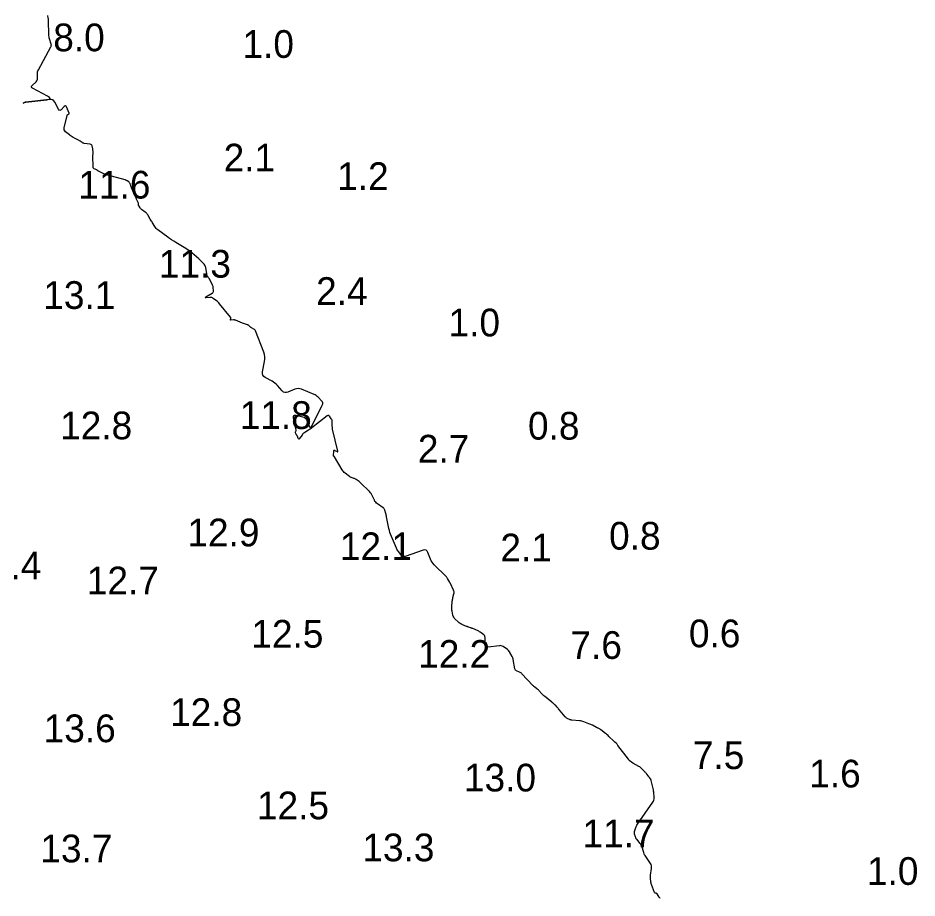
# Model space of a CAD drawing. Extents: x 815352 to 820877, y 582403 to 597439.
# Drawn here: x 817522 to 817684.3, y 596217.5 to 596376.3 of the extents above; entities that cross this region are included whole.
import ezdxf

# ---------------------------------------------------------------- set-up
doc = ezdxf.new("R2010")
doc.units = 0
doc.layers.add('V-CONT-EL12', color=7, linetype='Continuous')
doc.layers.add('V-TOPO-SOUN', color=7, linetype='Continuous')

msp = doc.modelspace()

# ---------------------------------------------------------------- linework, layer by layer
at = {"layer": 'V-CONT-EL12'}
msp.add_lwpolyline([(817637.89, 596217.43), (817637.81, 596217.54), (817637.73, 596217.65), (817637.33, 596218.27), (817637.3, 596218.31), (817637.27, 596218.34), (817637.23, 596218.36), (817637.19, 596218.37), (817637.01, 596218.41), (817636.97, 596218.42), (817636.94, 596218.44), (817636.91, 596218.47), (817636.89, 596218.51), (817636.33, 596219.95), (817636.29, 596220.09), (817636.25, 596220.22), (817636.22, 596220.36), (817636.21, 596220.5), (817636.17, 596221.07), (817636.16, 596221.22), (817636.16, 596221.36), (817636.17, 596221.5), (817636.18, 596221.64), (817636.34, 596222.85), (817636.36, 596223.09), (817636.32, 596223.32), (817636.25, 596223.55), (817636.14, 596223.76), (817635.21, 596225.17), (817635.1, 596225.34), (817635.01, 596225.52), (817634.93, 596225.71), (817634.87, 596225.9), (817634.63, 596226.69), (817634.56, 596226.87), (817634.48, 596227.05), (817634.38, 596227.22), (817634.26, 596227.38), (817633.66, 596228.13), (817633.59, 596228.23), (817633.53, 596228.33), (817633.48, 596228.44), (817633.43, 596228.56), (817633.28, 596229.03), (817633.25, 596229.15), (817633.24, 596229.26), (817633.25, 596229.38), (817633.28, 596229.5), (817633.49, 596230.23), (817633.55, 596230.39), (817633.61, 596230.54), (817633.69, 596230.68), (817633.78, 596230.82), (817636.56, 596234.79), (817636.67, 596234.99), (817636.75, 596235.2), (817636.79, 596235.42), (817636.8, 596235.65), (817636.74, 596236.6), (817636.72, 596236.83), (817636.69, 596237.06), (817636.65, 596237.29), (817636.59, 596237.52), (817636.28, 596238.72), (817636.26, 596238.8), (817636.23, 596238.87), (817636.19, 596238.94), (817636.15, 596239.01), (817635.96, 596239.26), (817635.92, 596239.33), (817635.87, 596239.39), (817635.82, 596239.45), (817635.77, 596239.52), (817635.48, 596239.9), (817635.42, 596239.98), (817635.35, 596240.06), (817635.28, 596240.14), (817635.21, 596240.22), (817634.62, 596240.84), (817634.49, 596240.96), (817634.35, 596241.07), (817634.21, 596241.17), (817634.06, 596241.26), (817632.95, 596241.87), (817632.73, 596242.01), (817632.52, 596242.17), (817632.33, 596242.36), (817632.16, 596242.56), (817630.28, 596245.04), (817630.11, 596245.26), (817629.93, 596245.46), (817629.74, 596245.66), (817629.55, 596245.85), (817628.65, 596246.68), (817628.49, 596246.82), (817628.34, 596246.96), (817628.19, 596247.09), (817628.03, 596247.22), (817627.18, 596247.9), (817627.13, 596247.95), (817627.07, 596247.98), (817627.01, 596248.02), (817626.95, 596248.05), (817626.69, 596248.17), (817626.62, 596248.19), (817626.56, 596248.23), (817626.5, 596248.26), (817626.43, 596248.29), (817625.66, 596248.7), (817625.51, 596248.78), (817625.36, 596248.85), (817625.2, 596248.92), (817625.04, 596248.98), (817624.15, 596249.32), (817623.95, 596249.39), (817623.74, 596249.45), (817623.53, 596249.49), (817623.32, 596249.51), (817621.98, 596249.62), (817621.86, 596249.64), (817621.76, 596249.66), (817621.65, 596249.69), (817621.54, 596249.74), (817621.13, 596249.94), (817621.04, 596249.99), (817620.94, 596250.06), (817620.86, 596250.13), (817620.78, 596250.21), (817619.56, 596251.68), (817619.5, 596251.75), (817619.43, 596251.83), (817619.37, 596251.9), (817619.3, 596251.97), (817618.99, 596252.3), (817618.94, 596252.35), (817618.89, 596252.4), (817618.84, 596252.45), (817618.78, 596252.49), (817618.57, 596252.68), (817618.51, 596252.73), (817618.46, 596252.77), (817618.41, 596252.82), (817618.35, 596252.86), (817617.02, 596253.92), (817616.89, 596254.03), (817616.76, 596254.14), (817616.64, 596254.26), (817616.52, 596254.38), (817616, 596254.97), (817615.92, 596255.06), (817615.83, 596255.14), (817615.74, 596255.21), (817615.65, 596255.29), (817615.28, 596255.57), (817615.19, 596255.64), (817615.1, 596255.72), (817615.01, 596255.8), (817614.93, 596255.88), (817612.94, 596257.98), (817612.84, 596258.07), (817612.73, 596258.16), (817612.62, 596258.23), (817612.49, 596258.28), (817611.97, 596258.49), (817611.86, 596258.55), (817611.77, 596258.64), (817611.71, 596258.74), (817611.67, 596258.87), (817611.39, 596260.55), (817611.36, 596260.7), (817611.31, 596260.85), (817611.25, 596260.99), (817611.19, 596261.13), (817610.79, 596261.85), (817610.76, 596261.9), (817610.73, 596261.95), (817610.69, 596261.99), (817610.66, 596262.03), (817610.52, 596262.2), (817610.48, 596262.24), (817610.44, 596262.27), (817610.4, 596262.31), (817610.35, 596262.34), (817609.54, 596262.89), (817609.39, 596262.98), (817609.22, 596263.04), (817609.06, 596263.06), (817608.88, 596263.05), (817606.77, 596262.81), (817606.54, 596262.82), (817606.38, 596262.9), (817606.29, 596263.05), (817606.26, 596263.27), (817606.28, 596264.53), (817606.27, 596264.68), (817606.23, 596264.81), (817606.15, 596264.93), (817606.04, 596265.03), (817605.56, 596265.4), (817605.43, 596265.49), (817605.31, 596265.57), (817605.17, 596265.65), (817605.03, 596265.71), (817604.07, 596266.13), (817603.98, 596266.17), (817603.89, 596266.21), (817603.79, 596266.24), (817603.7, 596266.27), (817603.32, 596266.4), (817603.23, 596266.43), (817603.14, 596266.46), (817603.05, 596266.5), (817602.96, 596266.53), (817602.1, 596266.9), (817601.93, 596266.99), (817601.77, 596267.08), (817601.62, 596267.19), (817601.48, 596267.31), (817600.85, 596267.91), (817600.73, 596268.05), (817600.63, 596268.2), (817600.55, 596268.37), (817600.5, 596268.55), (817600.34, 596269.3), (817600.31, 596269.49), (817600.29, 596269.68), (817600.28, 596269.87), (817600.29, 596270.06), (817600.38, 596271.07), (817600.39, 596271.24), (817600.42, 596271.41), (817600.45, 596271.58), (817600.49, 596271.75), (817600.66, 596272.42), (817600.69, 596272.59), (817600.69, 596272.75), (817600.66, 596272.92), (817600.6, 596273.08), (817600.04, 596274.3), (817600.03, 596274.32), (817600.02, 596274.34), (817600, 596274.37), (817599.98, 596274.39), (817599.92, 596274.48), (817599.9, 596274.5), (817599.89, 596274.52), (817599.87, 596274.54), (817599.86, 596274.57), (817599.53, 596275.17), (817599.47, 596275.28), (817599.4, 596275.38), (817599.33, 596275.47), (817599.24, 596275.56), (817597.13, 596277.63), (817596.91, 596277.86), (817596.73, 596278.12), (817596.57, 596278.39), (817596.44, 596278.68), (817595.98, 596279.89), (817595.84, 596280.14), (817595.66, 596280.29), (817595.42, 596280.34), (817595.14, 596280.29), (817591.85, 596279.17), (817591.67, 596279.13), (817591.5, 596279.15), (817591.35, 596279.22), (817591.21, 596279.35), (817590.7, 596279.98), (817590.58, 596280.14), (817590.47, 596280.3), (817590.38, 596280.48), (817590.29, 596280.66), (817589.24, 596283.18), (817589.11, 596283.51), (817589.01, 596283.84), (817588.91, 596284.18), (817588.84, 596284.52), (817588.51, 596286.28), (817588.48, 596286.43), (817588.44, 596286.58), (817588.41, 596286.73), (817588.37, 596286.88), (817588.21, 596287.49), (817588.16, 596287.63), (817588.08, 596287.76), (817587.99, 596287.87), (817587.87, 596287.96), (817586.89, 596288.63), (817586.71, 596288.77), (817586.56, 596288.93), (817586.42, 596289.1), (817586.31, 596289.3), (817585.78, 596290.42), (817585.74, 596290.48), (817585.71, 596290.54), (817585.67, 596290.6), (817585.62, 596290.65), (817585.44, 596290.87), (817585.39, 596290.92), (817585.34, 596290.97), (817585.29, 596291.02), (817585.24, 596291.07), (817583.99, 596292.29), (817583.88, 596292.38), (817583.77, 596292.48), (817583.66, 596292.57), (817583.54, 596292.66), (817583.01, 596293.03), (817582.92, 596293.09), (817582.82, 596293.15), (817582.72, 596293.2), (817582.62, 596293.24), (817582.2, 596293.39), (817582.09, 596293.43), (817581.99, 596293.48), (817581.9, 596293.54), (817581.81, 596293.6), (817581.01, 596294.19), (817580.85, 596294.32), (817580.71, 596294.46), (817580.59, 596294.62), (817580.48, 596294.79), (817579.11, 596297.16), (817579.1, 596297.17), (817579.08, 596297.19), (817579.06, 596297.2), (817579.04, 596297.21), (817578.96, 596297.25), (817578.94, 596297.26), (817578.93, 596297.27), (817578.92, 596297.29), (817578.92, 596297.31), (817578.97, 596298.18), (817578.99, 596298.27), (817579.03, 596298.31), (817579.1, 596298.32), (817579.18, 596298.29), (817579.57, 596298.08), (817579.65, 596298.04), (817579.7, 596298.05), (817579.72, 596298.1), (817579.71, 596298.18), (817578.78, 596302.15), (817578.75, 596302.31), (817578.73, 596302.47), (817578.71, 596302.63), (817578.71, 596302.79), (817578.71, 596303.45), (817578.69, 596303.6), (817578.66, 596303.74), (817578.61, 596303.87), (817578.53, 596304), (817578.18, 596304.49), (817578.08, 596304.58), (817577.99, 596304.62), (817577.88, 596304.61), (817577.76, 596304.54), (817575.04, 596302.38), (817574.89, 596302.26), (817574.73, 596302.15), (817574.58, 596302.04), (817574.42, 596301.94), (817573.74, 596301.52), (817573.6, 596301.42), (817573.47, 596301.32), (817573.35, 596301.2), (817573.25, 596301.07), (817572.74, 596300.4), (817572.69, 596300.34), (817572.65, 596300.33), (817572.61, 596300.36), (817572.57, 596300.42), (817572.41, 596300.89), (817572.4, 596300.92), (817572.38, 596300.95), (817572.37, 596300.98), (817572.34, 596301.01), (817572.26, 596301.11), (817572.23, 596301.14), (817572.21, 596301.17), (817572.2, 596301.2), (817572.18, 596301.23), (817572.08, 596301.49), (817572.06, 596301.53), (817572.06, 596301.56), (817572.07, 596301.6), (817572.08, 596301.64), (817572.15, 596301.79), (817572.17, 596301.83), (817572.17, 596301.86), (817572.17, 596301.9), (817572.17, 596301.94), (817571.69, 596304.2), (817571.68, 596304.45), (817571.75, 596304.61), (817571.91, 596304.68), (817572.16, 596304.65), (817573.39, 596304.36), (817573.64, 596304.27), (817573.85, 596304.13), (817574.01, 596303.94), (817574.13, 596303.71), (817574.54, 596302.66), (817574.64, 596302.47), (817574.75, 596302.4), (817574.87, 596302.45), (817574.99, 596302.64), (817576.91, 596306.46), (817576.99, 596306.67), (817576.99, 596306.86), (817576.93, 596307.04), (817576.8, 596307.21), (817576.16, 596307.88), (817576, 596308.04), (817575.82, 596308.18), (817575.62, 596308.3), (817575.42, 596308.39), (817573.15, 596309.34), (817572.84, 596309.43), (817572.54, 596309.46), (817572.24, 596309.43), (817571.93, 596309.33), (817570.71, 596308.8), (817570.42, 596308.72), (817570.16, 596308.73), (817569.91, 596308.83), (817569.69, 596309.03), (817568.83, 596309.99), (817568.61, 596310.22), (817568.37, 596310.43), (817568.11, 596310.62), (817567.84, 596310.78), (817566.61, 596311.46), (817566.35, 596311.65), (817566.19, 596311.88), (817566.12, 596312.15), (817566.14, 596312.46), (817566.5, 596314.35), (817566.55, 596314.77), (817566.54, 596315.19), (817566.47, 596315.6), (817566.35, 596316.01), (817564.85, 596319.9), (817564.81, 596319.99), (817564.74, 596320.08), (817564.67, 596320.14), (817564.57, 596320.2), (817564.11, 596320.42), (817564.05, 596320.46), (817563.98, 596320.5), (817563.92, 596320.55), (817563.87, 596320.6), (817563.65, 596320.82), (817563.6, 596320.87), (817563.54, 596320.92), (817563.47, 596320.95), (817563.4, 596320.98), (817562.66, 596321.22), (817562.51, 596321.27), (817562.37, 596321.32), (817562.22, 596321.37), (817562.08, 596321.43), (817561.22, 596321.78), (817561.13, 596321.81), (817561.04, 596321.83), (817560.95, 596321.84), (817560.86, 596321.84), (817560.42, 596321.8), (817560.37, 596321.8), (817560.34, 596321.82), (817560.33, 596321.85), (817560.33, 596321.9), (817560.39, 596322.11), (817560.4, 596322.17), (817560.39, 596322.21), (817560.38, 596322.26), (817560.35, 596322.31), (817558.35, 596324.77), (817558.23, 596324.91), (817558.1, 596325.04), (817557.97, 596325.16), (817557.83, 596325.27), (817557.22, 596325.72), (817557.09, 596325.8), (817556.94, 596325.86), (817556.78, 596325.89), (817556.62, 596325.9), (817555.95, 596325.85), (817555.82, 596325.85), (817555.77, 596325.88), (817555.8, 596325.92), (817555.9, 596326), (817557.04, 596326.64), (817557.15, 596326.72), (817557.23, 596326.83), (817557.27, 596326.95), (817557.27, 596327.09), (817557.21, 596327.7), (817557.19, 596327.85), (817557.15, 596328), (817557.1, 596328.14), (817557.03, 596328.28), (817556.46, 596329.3), (817556.43, 596329.35), (817556.41, 596329.39), (817556.37, 596329.43), (817556.34, 596329.47), (817556.2, 596329.63), (817556.17, 596329.68), (817556.15, 596329.72), (817556.13, 596329.77), (817556.12, 596329.82), (817555.87, 596331.28), (817555.83, 596331.45), (817555.77, 596331.6), (817555.69, 596331.75), (817555.58, 596331.88), (817555.12, 596332.39), (817555, 596332.51), (817554.88, 596332.63), (817554.75, 596332.75), (817554.62, 596332.86), (817553.35, 596333.94), (817553.09, 596334.15), (817552.82, 596334.35), (817552.54, 596334.53), (817552.26, 596334.71), (817550.45, 596335.81), (817550.08, 596336.04), (817549.71, 596336.28), (817549.35, 596336.52), (817549, 596336.78), (817547.21, 596338.1), (817547.06, 596338.22), (817546.92, 596338.36), (817546.79, 596338.51), (817546.68, 596338.67), (817546.27, 596339.35), (817546.17, 596339.52), (817546.07, 596339.68), (817545.97, 596339.85), (817545.86, 596340.02), (817545.41, 596340.79), (817545.32, 596340.93), (817545.21, 596341.06), (817545.09, 596341.17), (817544.96, 596341.28), (817544.3, 596341.75), (817544.22, 596341.82), (817544.15, 596341.89), (817544.08, 596341.97), (817544.02, 596342.05), (817543.73, 596342.53), (817543.72, 596342.56), (817543.71, 596342.59), (817543.71, 596342.62), (817543.71, 596342.65), (817543.75, 596342.78), (817543.75, 596342.81), (817543.75, 596342.84), (817543.75, 596342.87), (817543.74, 596342.9), (817543.38, 596343.65), (817543.32, 596343.79), (817543.26, 596343.92), (817543.19, 596344.06), (817543.13, 596344.19), (817542.53, 596345.53), (817542.48, 596345.63), (817542.44, 596345.74), (817542.4, 596345.85), (817542.36, 596345.96), (817542.2, 596346.44), (817542.16, 596346.53), (817542.12, 596346.6), (817542.06, 596346.67), (817541.99, 596346.73), (817541.68, 596346.94), (817541.61, 596346.99), (817541.53, 596347.03), (817541.44, 596347.07), (817541.35, 596347.1), (817537.96, 596348.05), (817537.8, 596348.1), (817537.65, 596348.15), (817537.5, 596348.21), (817537.35, 596348.28), (817536.51, 596348.68), (817536.48, 596348.69), (817536.45, 596348.71), (817536.42, 596348.73), (817536.4, 596348.75), (817536.3, 596348.83), (817536.27, 596348.85), (817536.25, 596348.87), (817536.22, 596348.89), (817536.19, 596348.9), (817535.73, 596349.1), (817535.65, 596349.14), (817535.6, 596349.2), (817535.57, 596349.28), (817535.56, 596349.36), (817535.57, 596349.77), (817535.57, 596349.86), (817535.57, 596349.96), (817535.56, 596350.06), (817535.56, 596350.16), (817535.5, 596350.67), (817535.49, 596350.78), (817535.48, 596350.9), (817535.48, 596351.02), (817535.48, 596351.14), (817535.52, 596352.17), (817535.52, 596352.31), (817535.51, 596352.44), (817535.49, 596352.58), (817535.46, 596352.71), (817535.34, 596353.24), (817535.3, 596353.35), (817535.23, 596353.44), (817535.14, 596353.51), (817535.02, 596353.54), (817533.94, 596353.69), (817533.84, 596353.72), (817533.74, 596353.75), (817533.64, 596353.79), (817533.54, 596353.85), (817533.18, 596354.09), (817533.08, 596354.15), (817532.99, 596354.21), (817532.9, 596354.27), (817532.8, 596354.32), (817531.93, 596354.79), (817531.76, 596354.89), (817531.59, 596355), (817531.42, 596355.11), (817531.26, 596355.24), (817530.57, 596355.81), (817530.43, 596355.96), (817530.34, 596356.13), (817530.31, 596356.31), (817530.33, 596356.51), (817530.84, 596358.74), (817530.85, 596358.79), (817530.88, 596358.83), (817530.91, 596358.87), (817530.96, 596358.9), (817531.15, 596359.01), (817531.18, 596359.04), (817531.21, 596359.07), (817531.21, 596359.11), (817531.2, 596359.16), (817530.76, 596360.27), (817530.68, 596360.42), (817530.58, 596360.48), (817530.47, 596360.46), (817530.33, 596360.36), (817529.77, 596359.78), (817529.64, 596359.67), (817529.51, 596359.65), (817529.4, 596359.71), (817529.3, 596359.85), (817528.6, 596361.14), (817528.44, 596361.38), (817528.23, 596361.53), (817527.98, 596361.62), (817527.69, 596361.62), (817523.41, 596361.13), (817523.27, 596361.11), (817523.14, 596361.07), (817523.02, 596361.01), (817522.9, 596360.93), (817523.02, 596361.01), (817523.14, 596361.07), (817523.27, 596361.11), (817523.41, 596361.13), (817527.16, 596361.56), (817527.6, 596361.65), (817527.77, 596361.79), (817527.66, 596361.99), (817527.28, 596362.23), (817524.61, 596363.64), (817524.45, 596363.75), (817524.39, 596363.88), (817524.42, 596364.02), (817524.54, 596364.16), (817525.23, 596364.83), (817525.36, 596364.97), (817525.44, 596365.13), (817525.49, 596365.3), (817525.5, 596365.48), (817525.47, 596366.26), (817525.48, 596366.44), (817525.51, 596366.63), (817525.57, 596366.81), (817525.65, 596366.98), (817527.93, 596371.14), (817527.94, 596371.17), (817527.96, 596371.21), (817527.97, 596371.24), (817527.97, 596371.28), (817527.99, 596371.43), (817528, 596371.47), (817528, 596371.5), (817527.99, 596371.54), (817527.98, 596371.58), (817527.68, 596372.59), (817527.63, 596372.77), (817527.6, 596372.95), (817527.57, 596373.14), (817527.56, 596373.33), (817527.5, 596375.83), (817527.49, 596375.95), (817527.48, 596376.08), (817527.46, 596376.2), (817527.44, 596376.32), (817527.35, 596376.8)], dxfattribs=at)

# ---------------------------------------------------------------- texts
at = {"layer": 'V-TOPO-SOUN'}
for s, p in [('8.0', (817528.34, 596370.32)), ('1.0', (817562.5, 596369.13)), ('2.1', (817559.1, 596348.63)), ('1.2', (817579.59, 596345.28)), ('11.6 ', (817532.87, 596343.74)), ('11.3 ', (817547.4, 596329.47)), ('2.4', (817575.79, 596324.55)), ('13.1 ', (817526.54, 596323.83)), ('1.0', (817599.7, 596318.87)), ('11.8 ', (817562, 596302.17)), ('12.8 ', (817529.58, 596300.3)), ('0.8', (817614.04, 596300.24)), ('2.7', (817594.16, 596296.1)), ('12.9 ', (817552.55, 596280.98)), ('0.8', (817628.68, 596280.39)), ('12.1 ', (817580.08, 596278.49)), ('2.1', (817609.06, 596278.26)), ('13.4 ', (817513.18, 596275.04)), ('12.7 ', (817534.4, 596272.32)), ('12.5 ', (817564.1, 596262.7)), ('0.6', (817643.09, 596262.77)), ('7.6', (817621.7, 596260.67)), ('12.2 ', (817594.21, 596259.06)), ('12.8 ', (817549.43, 596248.56)), ('13.6 ', (817526.61, 596245.64)), ('7.5', (817643.8, 596240.79)), ('1.6', (817664.81, 596237.47)), ('13.0 ', (817602.48, 596236.75)), ('12.5 ', (817565.11, 596231.73)), ('11.7 ', (817623.87, 596226.68)), ('13.7 ', (817526.01, 596223.96)), ('13.3 ', (817584.14, 596224.15)), ('1.0', (817675.23, 596219.89))]:
    msp.add_text(s, height=5, dxfattribs=at).set_placement(p)

doc.saveas('drawing.dxf')
